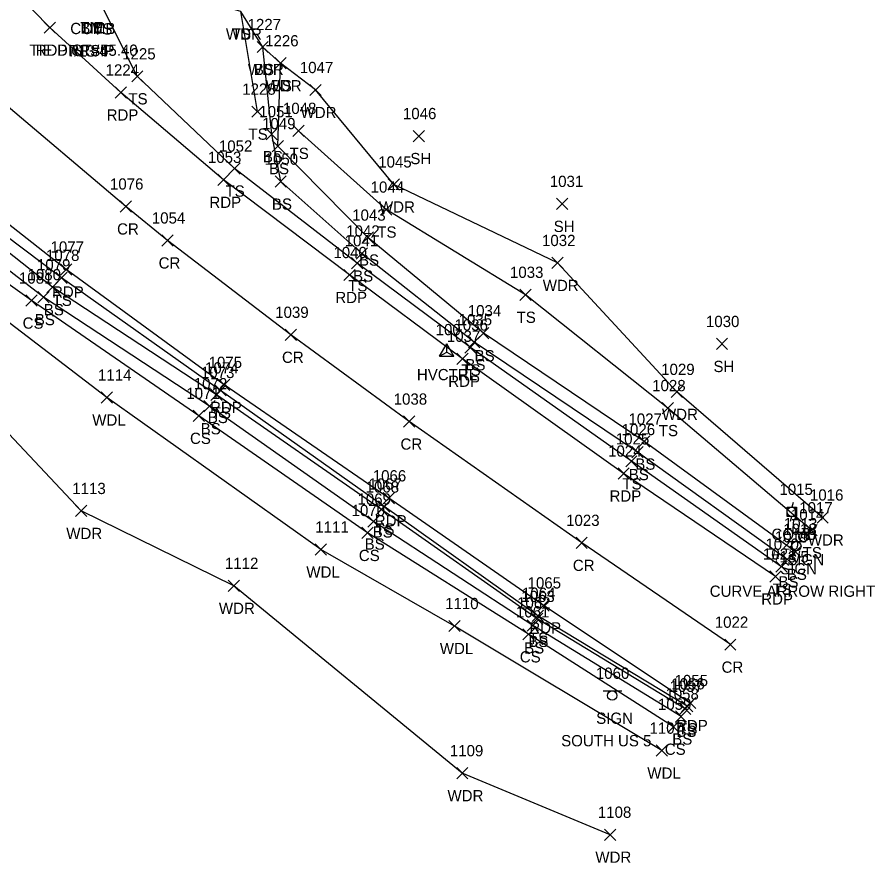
# Model space of a CAD drawing. Extents: x 1620157 to 1620595, y 115111 to 117885.
# Drawn here: x 1620442.4 to 1620594.9, y 115111.1 to 115261.5 of the extents above; entities that cross this region are included whole.
import ezdxf

# ---------------------------------------------------------------- set-up
doc = ezdxf.new("R2010")
doc.units = 0
for name, color, linetype in [('C_A', 7, 'Continuous'), ('C_C', 7, 'Continuous'), ('C_I', 7, 'Continuous'), ('CPSM', 7, 'Continuous'), ('L_A', 7, 'Continuous'), ('L_I', 7, 'Continuous'), ('L_TIC', 7, 'Continuous'), ('LAWA', 7, 'Continuous'), ('LELB', 7, 'Continuous'), ('P_A', 7, 'Continuous'), ('P_I', 7, 'Continuous'), ('P_TIC', 7, 'Continuous'), ('PET', 7, 'Continuous'), ('PRC', 7, 'Continuous'), ('S_A', 7, 'Continuous'), ('S_C', 7, 'Continuous'), ('S_I', 7, 'Continuous'), ('SSGN', 7, 'Continuous'), ('U_A', 7, 'Continuous'), ('U_C', 7, 'Continuous'), ('U_I', 7, 'Continuous'), ('UP', 7, 'Continuous')]:
    doc.layers.add(name, color=color, linetype=linetype)

msp = doc.modelspace()

# ---------------------------------------------------------------- linework, layer by layer
at = {"layer": 'CPSM'}
for p, q in [((1620517.51, 115201.21), (1620518.76, 115203.37)), ((1620520.01, 115201.21), (1620518.76, 115203.37)), ((1620518.76, 115201.93), (1620518.76, 115203.37)), ((1620517.51, 115201.21), (1620518.76, 115201.93)), ((1620517.51, 115201.21), (1620520.01, 115201.21)), ((1620518.76, 115201.93), (1620518.76, 115201.93)), ((1620518.76, 115201.93), (1620520.01, 115201.21))]:
    msp.add_line(p, q, dxfattribs=at)
at = {"layer": 'L_TIC'}
for points in [[(1620485.05, 115255.17), (1620487.05, 115257.17)], [(1620487.05, 115255.17), (1620485.05, 115257.17)], [(1620485.05, 115255.17), (1620487.05, 115257.17)], [(1620487.05, 115255.17), (1620485.05, 115257.17)], [(1620488.23, 115252.28), (1620490.23, 115254.28)], [(1620490.23, 115252.28), (1620488.23, 115254.28)], [(1620488.23, 115252.28), (1620490.23, 115254.28)], [(1620490.23, 115252.28), (1620488.23, 115254.28)], [(1620462.76, 115249.96), (1620464.76, 115251.96)], [(1620464.76, 115249.96), (1620462.76, 115251.96)], [(1620494.42, 115247.53), (1620496.42, 115249.53)], [(1620496.42, 115247.53), (1620494.42, 115249.53)], [(1620484.11, 115243.68), (1620486.11, 115245.68)], [(1620486.11, 115243.68), (1620484.11, 115245.68)], [(1620491.42, 115240.26), (1620493.42, 115242.26)], [(1620493.42, 115240.26), (1620491.42, 115242.26)], [(1620486.65, 115239.68), (1620488.65, 115241.68)], [(1620488.65, 115239.68), (1620486.65, 115241.68)], [(1620512.81, 115239.34), (1620514.81, 115241.34)], [(1620514.81, 115239.34), (1620512.81, 115241.34)], [(1620487.72, 115237.55), (1620489.72, 115239.55)], [(1620489.72, 115237.55), (1620487.72, 115239.55)], [(1620480.03, 115233.56), (1620482.03, 115235.56)], [(1620482.03, 115233.56), (1620480.03, 115235.56)], [(1620488.25, 115231.24), (1620490.25, 115233.24)], [(1620490.25, 115231.24), (1620488.25, 115233.24)], [(1620508.36, 115230.74), (1620510.36, 115232.74)], [(1620510.36, 115230.74), (1620508.36, 115232.74)], [(1620507.01, 115226.27), (1620509.01, 115228.27)], [(1620509.01, 115226.27), (1620507.01, 115228.27)], [(1620538.29, 115227.28), (1620540.29, 115229.28)], [(1620540.29, 115227.28), (1620538.29, 115229.28)], [(1620503.73, 115221.29), (1620505.73, 115223.29)], [(1620505.73, 115221.29), (1620503.73, 115223.29)], [(1620502.68, 115218.46), (1620504.68, 115220.46)], [(1620504.68, 115218.46), (1620502.68, 115220.46)], [(1620501.84, 115216.73), (1620503.84, 115218.73)], [(1620503.84, 115216.73), (1620501.84, 115218.73)], [(1620537.48, 115216.78), (1620539.48, 115218.78)], [(1620539.48, 115216.78), (1620537.48, 115218.78)], [(1620449.29, 115214.14), (1620451.29, 115216.14)], [(1620451.29, 115214.14), (1620449.29, 115216.14)], [(1620447.7, 115212.47), (1620449.7, 115214.47)], [(1620449.7, 115212.47), (1620447.7, 115214.47)], [(1620531.78, 115211.12), (1620533.78, 115213.12)], [(1620533.78, 115211.12), (1620531.78, 115213.12)], [(1620443.93, 115210.09), (1620445.93, 115212.09)], [(1620445.93, 115210.09), (1620443.93, 115212.09)], [(1620446.1, 115210.71), (1620448.1, 115212.71)], [(1620448.1, 115210.71), (1620446.1, 115212.71)], [(1620524.28, 115204.28), (1620526.28, 115206.28)], [(1620526.28, 115204.28), (1620524.28, 115206.28)], [(1620521.97, 115201.75), (1620523.97, 115203.75)], [(1620523.97, 115201.75), (1620521.97, 115203.75)], [(1620522.65, 115202.69), (1620524.65, 115204.69)], [(1620524.65, 115202.69), (1620522.65, 115204.69)], [(1620566.71, 115202.38), (1620568.71, 115204.38)], [(1620568.71, 115202.38), (1620566.71, 115204.38)], [(1620477.57, 115194.13), (1620479.57, 115196.13)], [(1620479.57, 115194.13), (1620477.57, 115196.13)], [(1620457.33, 115192.85), (1620459.33, 115194.85)], [(1620459.33, 115192.85), (1620457.33, 115194.85)], [(1620476.85, 115193.31), (1620478.85, 115195.31)], [(1620478.85, 115193.31), (1620476.85, 115195.31)], [(1620558.67, 115193.86), (1620560.67, 115195.86)], [(1620560.67, 115193.86), (1620558.67, 115195.86)], [(1620475.58, 115191.31), (1620477.58, 115193.31)], [(1620477.58, 115191.31), (1620475.58, 115193.31)], [(1620557.06, 115190.98), (1620559.06, 115192.98)], [(1620559.06, 115190.98), (1620557.06, 115192.98)], [(1620473.68, 115189.6), (1620475.68, 115191.6)], [(1620475.68, 115189.6), (1620473.68, 115191.6)], [(1620552.85, 115185.02), (1620554.85, 115187.02)], [(1620554.85, 115185.02), (1620552.85, 115187.02)], [(1620551.69, 115183.16), (1620553.69, 115185.16)], [(1620553.69, 115183.16), (1620551.69, 115185.16)], [(1620550.59, 115181.51), (1620552.59, 115183.51)], [(1620552.59, 115181.51), (1620550.59, 115183.51)], [(1620452.76, 115172.69), (1620454.76, 115174.69)], [(1620454.76, 115172.69), (1620452.76, 115174.69)], [(1620506.17, 115172.96), (1620508.17, 115174.96)], [(1620508.17, 115172.96), (1620506.17, 115174.96)], [(1620506.65, 115173.47), (1620508.65, 115175.47)], [(1620508.65, 115173.47), (1620506.65, 115175.47)], [(1620584.6, 115171.53), (1620586.6, 115173.53)], [(1620586.6, 115171.53), (1620584.6, 115173.53)], [(1620504.73, 115170.81), (1620506.73, 115172.81)], [(1620506.73, 115170.81), (1620504.73, 115172.81)], [(1620503.7, 115168.78), (1620505.7, 115170.78)], [(1620505.7, 115168.78), (1620503.7, 115170.78)], [(1620582.63, 115169.26), (1620584.63, 115171.26)], [(1620584.63, 115169.26), (1620582.63, 115171.26)], [(1620495.39, 115165.83), (1620497.39, 115167.83)], [(1620497.39, 115165.83), (1620495.39, 115167.83)], [(1620579.79, 115165.43), (1620581.79, 115167.43)], [(1620581.79, 115165.43), (1620579.79, 115167.43)], [(1620578.3, 115164.08), (1620580.3, 115166.08)], [(1620580.3, 115164.08), (1620578.3, 115166.08)], [(1620577.28, 115162.78), (1620579.28, 115164.78)], [(1620579.28, 115162.78), (1620577.28, 115164.78)], [(1620479.9, 115159.38), (1620481.9, 115161.38)], [(1620481.9, 115159.38), (1620479.9, 115161.38)], [(1620533.84, 115153.5), (1620535.84, 115155.5)], [(1620535.84, 115153.5), (1620533.84, 115155.5)], [(1620533.96, 115154.05), (1620535.96, 115156.05)], [(1620535.96, 115154.05), (1620533.96, 115156.05)], [(1620519.13, 115152.23), (1620521.13, 115154.23)], [(1620521.13, 115152.23), (1620519.13, 115154.23)], [(1620533.09, 115152.34), (1620535.09, 115154.34)], [(1620535.09, 115152.34), (1620533.09, 115154.34)], [(1620532.32, 115150.76), (1620534.32, 115152.76)], [(1620534.32, 115150.76), (1620532.32, 115152.76)], [(1620560.51, 115137.96), (1620562.51, 115139.96)], [(1620562.51, 115137.96), (1620560.51, 115139.96)], [(1620559.42, 115136.14), (1620561.42, 115138.14)], [(1620561.42, 115136.14), (1620559.42, 115138.14)], [(1620560.16, 115137.52), (1620562.16, 115139.52)], [(1620562.16, 115137.52), (1620560.16, 115139.52)], [(1620558.1, 115134.33), (1620560.1, 115136.33)], [(1620560.1, 115134.33), (1620558.1, 115136.33)], [(1620556.01, 115130.08), (1620558.01, 115132.08)], [(1620558.01, 115130.08), (1620556.01, 115132.08)], [(1620520.54, 115126.07), (1620522.54, 115128.07)], [(1620522.54, 115126.07), (1620520.54, 115128.07)], [(1620546.83, 115115.13), (1620548.83, 115117.13)], [(1620548.83, 115115.13), (1620546.83, 115117.13)]]:
    msp.add_lwpolyline(points, dxfattribs=at)
at = {"layer": 'LAWA'}
for points in [[(1620585.6, 115172.53), (1620559.67, 115194.86), (1620538.48, 115217.78), (1620509.36, 115231.74), (1620495.42, 115248.53), (1620489.23, 115253.28), (1620486.05, 115256.17), (1620482.15, 115262.48), (1620465.14, 115267.42), (1620446.62, 115281.88), (1620471.87, 115275.77)], [(1620547.83, 115116.13), (1620521.54, 115127.07), (1620480.9, 115160.38), (1620453.76, 115173.69), (1620425.3, 115204), (1620404.55, 115226.87), (1620410.63, 115234.71)], [(1620557.01, 115131.08), (1620520.13, 115153.23), (1620496.39, 115166.83), (1620458.33, 115193.85), (1620435.52, 115211.3), (1620410.63, 115234.71)]]:
    msp.add_lwpolyline(points, dxfattribs=at)
at = {"layer": 'LELB'}
for points in [[(1620578.28, 115163.78), (1620551.59, 115182.51), (1620522.97, 115202.75), (1620502.84, 115217.73), (1620481.03, 115234.56), (1620463.76, 115250.96), (1620457.5, 115263.38), (1620433.25, 115280.27), (1620427.72, 115280.56)], [(1620485.11, 115244.68), (1620482.15, 115262.48)], [(1620579.3, 115165.08), (1620552.69, 115184.16), (1620523.65, 115203.69), (1620503.68, 115219.46), (1620489.25, 115232.24), (1620487.65, 115240.68), (1620486.05, 115256.17)], [(1620580.79, 115166.43), (1620553.85, 115186.02), (1620525.28, 115205.28), (1620504.73, 115222.29), (1620488.72, 115238.55), (1620489.23, 115253.28)], [(1620561.51, 115138.96), (1620534.96, 115155.05), (1620507.65, 115174.47), (1620478.57, 115195.13), (1620450.29, 115215.14), (1620426.37, 115233.17), (1620402.89, 115250.56), (1620398.98, 115249.07), (1620390.86, 115249.31)], [(1620561.16, 115138.52), (1620534.84, 115154.5), (1620507.17, 115173.96), (1620477.85, 115194.31), (1620448.7, 115213.47), (1620425.33, 115231.88), (1620402.18, 115248.57), (1620401.45, 115248.07), (1620400.59, 115247.68), (1620390.86, 115249.31)], [(1620560.42, 115137.14), (1620534.09, 115153.34), (1620505.73, 115171.81), (1620476.58, 115192.31), (1620447.1, 115211.71), (1620423.01, 115230.26), (1620403.93, 115244.65), (1620370, 115241.95), (1620354.86, 115237.37), (1620340.88, 115232.73)], [(1620559.1, 115135.33), (1620533.32, 115151.76), (1620504.7, 115169.78), (1620474.68, 115190.6), (1620444.93, 115211.09), (1620421.44, 115227.85), (1620403.77, 115241.77)], [(1620583.63, 115170.26), (1620558.06, 115191.98), (1620532.78, 115212.12), (1620508.01, 115227.27), (1620492.42, 115241.26)]]:
    msp.add_lwpolyline(points, dxfattribs=at)
at = {"layer": 'P_TIC'}
for points in [[(1620447.19, 115258.61), (1620449.19, 115260.61)], [(1620449.19, 115258.61), (1620447.19, 115260.61)], [(1620459.81, 115247.09), (1620461.81, 115249.09)], [(1620461.81, 115247.09), (1620459.81, 115249.09)], [(1620478.08, 115231.56), (1620480.08, 115233.56)], [(1620480.08, 115231.56), (1620478.08, 115233.56)], [(1620460.73, 115226.82), (1620462.73, 115228.82)], [(1620462.73, 115226.82), (1620460.73, 115228.82)], [(1620468.11, 115220.78), (1620470.11, 115222.78)], [(1620470.11, 115220.78), (1620468.11, 115222.78)], [(1620450.1, 115215.62), (1620452.1, 115217.62)], [(1620452.1, 115215.62), (1620450.1, 115217.62)], [(1620500.47, 115214.64), (1620502.47, 115216.64)], [(1620502.47, 115214.64), (1620500.47, 115216.64)], [(1620490.05, 115204.01), (1620492.05, 115206.01)], [(1620492.05, 115204.01), (1620490.05, 115206.01)], [(1620520.55, 115199.75), (1620522.55, 115201.75)], [(1620522.55, 115199.75), (1620520.55, 115201.75)], [(1620478.2, 115195.11), (1620480.2, 115197.11)], [(1620480.2, 115195.11), (1620478.2, 115197.11)], [(1620511.11, 115188.58), (1620513.11, 115190.58)], [(1620513.11, 115188.58), (1620511.11, 115190.58)], [(1620549.22, 115179.34), (1620551.22, 115181.34)], [(1620551.22, 115179.34), (1620549.22, 115181.34)], [(1620507.49, 115174.94), (1620509.49, 115176.94)], [(1620509.49, 115174.94), (1620507.49, 115176.94)], [(1620541.76, 115167.02), (1620543.76, 115169.02)], [(1620543.76, 115167.02), (1620541.76, 115169.02)], [(1620576.2, 115161.04), (1620578.2, 115163.04)], [(1620578.2, 115161.04), (1620576.2, 115163.04)], [(1620534.96, 115155.9), (1620536.96, 115157.9)], [(1620536.96, 115155.9), (1620534.96, 115157.9)], [(1620568.19, 115148.92), (1620570.19, 115150.92)], [(1620570.19, 115148.92), (1620568.19, 115150.92)], [(1620561.04, 115138.54), (1620563.04, 115140.54)], [(1620563.04, 115138.54), (1620561.04, 115140.54)]]:
    msp.add_lwpolyline(points, dxfattribs=at)
at = {"layer": 'PET'}
for points in [[(1620562.04, 115139.54), (1620535.96, 115156.9), (1620508.49, 115175.94), (1620479.2, 115196.11), (1620451.1, 115216.62), (1620428.04, 115234.7), (1620407.2, 115256.44), (1620380.21, 115287.87), (1620366.18, 115309.19), (1620356.59, 115324.56), (1620350.49, 115341.93), (1620344.69, 115361.16), (1620336.51, 115388.61), (1620345.69, 115391.55), (1620355.3, 115394.86)], [(1620577.2, 115162.04), (1620550.22, 115180.34), (1620521.55, 115200.75), (1620501.47, 115215.64), (1620479.08, 115232.56), (1620460.81, 115248.09), (1620448.19, 115259.61), (1620427.72, 115280.56), (1620407.74, 115305.05), (1620395.06, 115322.87), (1620383.52, 115342.08), (1620378.47, 115348.99), (1620371.95, 115360.23), (1620366.09, 115370.96), (1620359.39, 115386.19), (1620355.3, 115394.86)]]:
    msp.add_lwpolyline(points, dxfattribs=at)
at = {"layer": 'PRC'}
msp.add_lwpolyline([(1620569.19, 115149.92), (1620542.76, 115168.02), (1620512.11, 115189.58), (1620491.05, 115205.01), (1620469.11, 115221.78), (1620461.73, 115227.82), (1620438.82, 115247.13), (1620418.59, 115266.65), (1620405.03, 115281.95), (1620392.88, 115297.86), (1620380.47, 115316.24), (1620370.64, 115332.81), (1620355.49, 115365.23), (1620348.1, 115384.58), (1620345.69, 115391.55)], dxfattribs=at)
at = {"layer": 'SSGN'}
for p, q in [((1620580.53, 115169.9), (1620583.86, 115169.9)), ((1620582.18, 115169.06), (1620582.18, 115169.06)), ((1620579.27, 115168.27), (1620582.6, 115168.27)), ((1620580.92, 115167.44), (1620580.92, 115167.44)), ((1620546.55, 115141.7), (1620549.89, 115141.7)), ((1620548.2, 115140.86), (1620548.2, 115140.86))]:
    msp.add_line(p, q, dxfattribs=at)
for centre in [(1620582.18, 115169.06), (1620580.92, 115167.44), (1620548.2, 115140.86)]:
    msp.add_circle(centre, 0.833, dxfattribs=at)
at = {"layer": 'UP'}
for p, q in [((1620580.36, 115175.21), (1620580.11, 115174.38)), ((1620579.28, 115172.71), (1620579.28, 115174.38)), ((1620579.28, 115174.38), (1620580.95, 115174.38)), ((1620580.11, 115173.54), (1620580.11, 115173.54)), ((1620580.95, 115174.38), (1620580.95, 115172.71)), ((1620580.95, 115172.71), (1620579.28, 115172.71)), ((1620579.86, 115171.88), (1620580.11, 115172.71))]:
    msp.add_line(p, q, dxfattribs=at)
msp.add_circle((1620580.11, 115173.54), 0.833, dxfattribs=at)

# ---------------------------------------------------------------- texts
at = {"layer": 'C_A'}
for s, p in [('TIE', (1620453.61, 115258.6)), ('BM', (1620453.62, 115258.53)), ('HVCTRL', (1620513.46, 115196.93))]:
    msp.add_text(s, height=2, dxfattribs=at).set_placement(p)
at = {"layer": 'C_C'}
for s, p in [('TIE DIST=55.40', (1620444.58, 115254.6)), ('RRSIP', (1620451.52, 115254.53))]:
    msp.add_text(s, height=2, dxfattribs=at).set_placement(p)
at = {"layer": 'C_I'}
msp.add_text('100', height=2, dxfattribs=at).set_placement((1620516.8, 115204.93))
at = {"layer": 'L_A'}
for s, p in [('TS', (1620455.91, 115258.38)), ('WDR', (1620479.51, 115257.48)), ('TS', (1620480.56, 115257.48)), ('WDR', (1620483.41, 115251.17)), ('BS', (1620484.49, 115251.17)), ('WDR', (1620486.59, 115248.28)), ('BS', (1620487.67, 115248.28)), ('TS', (1620462.17, 115245.96)), ('WDR', (1620492.78, 115243.53)), ('TS', (1620483.52, 115239.68)), ('BS', (1620486.09, 115235.68)), ('TS', (1620490.83, 115236.26)), ('SH', (1620512.3, 115235.34)), ('BS', (1620487.16, 115233.55)), ('TS', (1620479.44, 115229.56)), ('BS', (1620487.69, 115227.24)), ('WDR', (1620506.72, 115226.74)), ('SH', (1620537.78, 115223.28)), ('TS', (1620506.42, 115222.27)), ('BS', (1620503.17, 115217.29)), ('BS', (1620502.12, 115214.46)), ('TS', (1620501.25, 115212.73)), ('WDR', (1620535.84, 115212.78)), ('TS', (1620448.7, 115210.14)), ('BS', (1620447.14, 115208.47)), ('BS', (1620445.54, 115206.71)), ('TS', (1620531.19, 115207.12)), ('CS', (1620443.37, 115206.09)), ('BS', (1620523.72, 115200.28)), ('BS', (1620522.09, 115198.69)), ('TS', (1620521.38, 115197.75)), ('SH', (1620566.19, 115198.38)), ('TS', (1620476.98, 115190.13)), ('WDR', (1620557.03, 115189.86)), ('WDL', (1620455.75, 115188.85)), ('BS', (1620476.29, 115189.31)), ('BS', (1620475.02, 115187.31)), ('TS', (1620556.47, 115186.98)), ('CS', (1620473.13, 115185.6)), ('BS', (1620552.29, 115181.02)), ('BS', (1620551.13, 115179.16)), ('TS', (1620550, 115177.51)), ('WDR', (1620451.13, 115168.69)), ('BS', (1620505.61, 115168.96)), ('TS', (1620506.06, 115169.47)), ('BS', (1620504.17, 115166.81)), ('WDR', (1620582.96, 115167.53)), ('TS', (1620582.04, 115165.26)), ('CS', (1620503.14, 115164.78)), ('WDL', (1620493.81, 115161.83)), ('BS', (1620579.23, 115161.43)), ('BS', (1620577.74, 115160.08)), ('TS', (1620576.69, 115158.78)), ('WDR', (1620478.26, 115155.38)), ('TS', (1620533.37, 115150.05)), ('BS', (1620532.53, 115148.34)), ('BS', (1620533.28, 115149.5)), ('WDL', (1620517.54, 115148.23)), ('CS', (1620531.76, 115146.76)), ('BS', (1620559.6, 115133.52)), ('TS', (1620559.92, 115133.96)), ('BS', (1620558.86, 115132.14)), ('CS', (1620557.54, 115130.33)), ('WDL', (1620554.43, 115126.08)), ('WDR', (1620518.9, 115122.07)), ('WDR', (1620545.19, 115111.13))]:
    msp.add_text(s, height=2, dxfattribs=at).set_placement(p)
at = {"layer": 'L_I'}
for s, p in [('1227', (1620483.36, 115259.17)), ('1227', (1620483.36, 115259.17)), ('1226', (1620486.48, 115256.28)), ('1226', (1620486.48, 115256.28)), ('1225', (1620461.07, 115253.96)), ('1047', (1620492.65, 115251.53)), ('1228', (1620482.41, 115247.68)), ('1051', (1620485.45, 115243.68)), ('1048', (1620489.65, 115244.26)), ('1046', (1620510.98, 115243.34)), ('1049', (1620485.94, 115241.55)), ('1052', (1620478.26, 115237.56)), ('1050', (1620486.39, 115235.24)), ('1045', (1620506.59, 115234.74)), ('1031', (1620537.09, 115231.28)), ('1044', (1620505.24, 115230.27)), ('1043', (1620501.96, 115225.29)), ('1042', (1620500.9, 115222.46)), ('1041', (1620500.63, 115220.73)), ('1032', (1620535.71, 115220.78)), ('1078', (1620447.52, 115218.14)), ('1079', (1620445.92, 115216.47)), ('1081', (1620442.72, 115214.09)), ('1080', (1620444.24, 115214.71)), ('1033', (1620530.01, 115215.12)), ('1034', (1620522.51, 115208.28)), ('1035', (1620520.88, 115206.69)), ('1030', (1620564.85, 115206.38)), ('1036', (1620520.14, 115205.75)), ('1073', (1620475.07, 115197.31)), ('1074', (1620475.8, 115198.13)), ('1029', (1620556.89, 115197.86)), ('1114', (1620456.77, 115196.85)), ('1072', (1620473.8, 115195.31)), ('1028', (1620555.29, 115194.98)), ('1071', (1620472.48, 115193.6)), ('1027', (1620551.07, 115189.02)), ('1026', (1620549.87, 115187.16)), ('1025', (1620548.82, 115185.51)), ('1067', (1620504.84, 115177.47)), ('1113', (1620452.2, 115176.69)), ('1068', (1620504.35, 115176.96)), ('1069', (1620502.9, 115174.81)), ('1016', (1620583.34, 115175.53)), ('1070', (1620501.85, 115172.78)), ('1017', (1620581.43, 115173.26)), ('1111', (1620495.4, 115169.83)), ('1019', (1620577.08, 115168.08)), ('1018', (1620578.59, 115169.43)), ('1020', (1620575.42, 115166.78)), ('1112', (1620479.34, 115163.38)), ('1063', (1620532.02, 115157.5)), ('1064', (1620532.14, 115158.05)), ('1110', (1620518.48, 115156.23)), ('1062', (1620531.27, 115156.34)), ('1061', (1620531.07, 115154.76)), ('1057', (1620558.39, 115141.52)), ('1056', (1620558.68, 115141.96)), ('1058', (1620557.64, 115140.14)), ('1059', (1620556.32, 115138.33)), ('1107', (1620554.81, 115134.08)), ('1109', (1620519.32, 115130.07)), ('1108', (1620545.63, 115119.13))]:
    msp.add_text(s, height=2, dxfattribs=at).set_placement(p)
at = {"layer": 'P_A'}
for s, p in [('RDP', (1620445.68, 115254.61)), ('RDP', (1620458.3, 115243.09)), ('RDP', (1620476.57, 115227.56)), ('CR', (1620460.16, 115222.82)), ('CR', (1620467.55, 115216.78)), ('RDP', (1620448.59, 115211.62)), ('RDP', (1620498.96, 115210.64)), ('CR', (1620489.48, 115200.01)), ('RDP', (1620519.04, 115195.75)), ('RDP', (1620476.69, 115191.11)), ('CR', (1620510.55, 115184.58)), ('RDP', (1620547.71, 115175.34)), ('RDP', (1620505.98, 115170.94)), ('CR', (1620541.19, 115163.02)), ('RDP', (1620574.68, 115157.04)), ('RDP', (1620533.45, 115151.9)), ('CR', (1620567.63, 115144.92)), ('RDP', (1620559.53, 115134.54))]:
    msp.add_text(s, height=2, dxfattribs=at).set_placement(p)
at = {"layer": 'P_I'}
for s, p in [('1224', (1620458.12, 115251.09)), ('1053', (1620476.31, 115235.56)), ('1076', (1620458.9, 115230.82)), ('1054', (1620466.34, 115224.78)), ('1077', (1620448.33, 115219.62)), ('1040', (1620498.62, 115218.64)), ('1039', (1620488.27, 115208.01)), ('1037', (1620518.78, 115203.75)), ('1075', (1620476.43, 115199.11)), ('1038', (1620509.34, 115192.58)), ('1024', (1620547.45, 115183.34)), ('1066', (1620505.62, 115178.94)), ('1023', (1620539.99, 115171.02)), ('1021', (1620574.99, 115165.04)), ('1065', (1620533.14, 115159.9)), ('1022', (1620566.42, 115152.92)), ('1055', (1620559.27, 115142.54))]:
    msp.add_text(s, height=2, dxfattribs=at).set_placement(p)
at = {"layer": 'S_A'}
for p in [(1620579.32, 115164.04), (1620578.05, 115162.42), (1620545.34, 115135.84)]:
    msp.add_text('SIGN', height=2, dxfattribs=at).set_placement(p)
at = {"layer": 'S_C'}
for s, p in [('CURVE ARROW RIGHT', (1620565.52, 115158.42)), ('SOUTH US 5', (1620539.11, 115131.84))]:
    msp.add_text(s, height=2, dxfattribs=at).set_placement(p)
at = {"layer": 'S_I'}
for s, p in [('1014', (1620579.95, 115172.04)), ('1013', (1620578.69, 115170.42)), ('1060', (1620545.28, 115143.84))]:
    msp.add_text(s, height=2, dxfattribs=at).set_placement(p)
at = {"layer": 'U_A'}
for p in [(1620451.84, 115258.46), (1620576.5, 115168.54)]:
    msp.add_text('COMB', height=2, dxfattribs=at).set_placement(p)
at = {"layer": 'U_C'}
for s, p in [('#13/4', (1620451.79, 115254.46)), ('#13/5', (1620576.44, 115164.54))]:
    msp.add_text(s, height=2, dxfattribs=at).set_placement(p)
at = {"layer": 'U_I'}
msp.add_text('1015', height=2, dxfattribs=at).set_placement((1620577.91, 115176.54))

doc.saveas('drawing.dxf')
